(* Logix 5000 project; controller Motion_Axis_AOIs_AMCI_RSLogix_V31 vendor 1 type 14 code 108 rev 31.11; software revision 31.02; part 6 of 7 *)

ADD_ON_INSTRUCTION AMCI_MSO_Enable   (* revision 1.0, vendor AMCI, ExecuteEnableInFalse *)
// AMCI Enable Driver
// Help:
// MSO_ENABLE:   Sends power to the motor.
// This instruction must only be used to change the existing enabled / disabled state of the AMCI motion device.  It MUST NOT be used in an unconditional rung because it will interfere with the other instructions sending data to the motion device
// AXIS INPUT DATA:  Input data from AMCI motion device.   Uses the AMCI_Motion_Axis_Input_Data User Defined Data Type.
// AXIS OUTPUT DATA; Output data from the AOI to the AMCI motion device.   Uses the AMCI_Motion_Axis_Output_Data User Defined Data Type.
// EN (Enable) Set when rung is true, Reset when rung is false
// DN (Done) Set when command is sent to the motion device.  Reset when the rung is false.
VAR_IN_OUT
   Axis_Input_Data : AMCI_Motion_Axis_Input_Data; {required}
   Axis_Output_Data : AMCI_Motion_Axis_Output_Data; {required}
END_VAR
VAR_OUTPUT
   EN : BOOL; {visible}   // set when rung with AOI is true
   DN : BOOL; {access Read Only, visible}   // set when reset error command sent to motion axis
END_VAR
VAR
   command_data_block : INT[10];
        [1]   // Command Bits LSW
        [3]   // Lower Target Position
        [5]   // Lower Programmed Speed
        [0]   // Command Bits MSW
        [2]   // Upper Target Position
        [4]   // Upper Programmed Speed
END_VAR

ROUTINE EnableInFalse   (* ladder *)
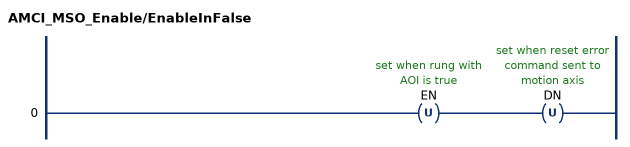
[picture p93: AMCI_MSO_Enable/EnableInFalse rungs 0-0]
   0: OTU(EN)OTU(DN);
END_ROUTINE

ROUTINE Logic   (* ladder *)
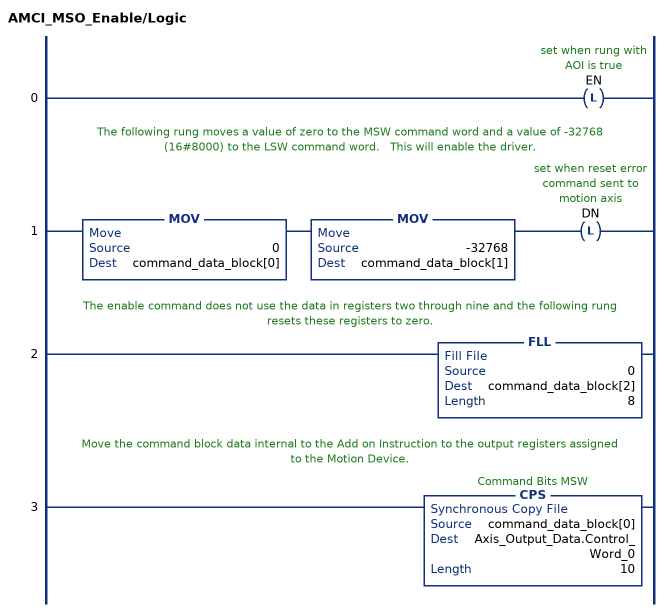
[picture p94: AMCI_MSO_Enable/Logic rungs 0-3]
   0: OTL(EN);
   // The following rung moves a value of zero to the MSW command word and a value of -32768 (16#8000) to the LSW command word.   This will enable the driver.
   1: MOV(0,command_data_block[0])MOV(-32768,command_data_block[1])OTL(DN);
   // The enable command does not use the data in registers two through nine and the following rung resets these registers to zero.
   2: FLL(0,command_data_block[2],8);
   // Move the command block data internal to the Add on Instruction to the output registers assigned to the Motion Device.
   3: CPS(command_data_block[0],Axis_Output_Data.Control_Word_0,10);
END_ROUTINE
END_ADD_ON_INSTRUCTION

VAR_GLOBAL   (* controller tags *)
   AMCI_Motion_Axis_run : DINT;
        .0   // set to run AMCI absolute or relative moves
        .1   // set to stop AMCI Motion
   AMCI_SD17060E2_input_data : AMCI_Motion_Axis_Input_Data;
   AMCI_SD17060E2_output_data : AMCI_Motion_Axis_Output_Data;
   AMCI_SD31045E2_input_data : AMCI_Motion_Axis_Input_Data;
   AMCI_SD31045E2_output_data : AMCI_Motion_Axis_Output_Data;
   AMCI_SD4840E2_input_data : AMCI_Motion_Axis_Input_Data;
   AMCI_SD4840E2_output_data : AMCI_Motion_Axis_Output_Data;
   AMCI_SMD17E2_input_data : AMCI_Motion_Axis_Input_Data;
   AMCI_SMD17E2_output_data : AMCI_Motion_Axis_Output_Data;
   AMCI_SMD23E2_input_data : AMCI_Motion_Axis_Input_Data;
   AMCI_SMD23E2_output_data : AMCI_Motion_Axis_Output_Data;
   AMCI_SMD34E2_input_data : AMCI_Motion_Axis_Input_Data;
   AMCI_SMD34E2_output_data : AMCI_Motion_Axis_Output_Data;
   AMCI_SV160E2_input_data : AMCI_Motion_Axis_Input_Data;
   AMCI_SV160E2_output_data : AMCI_Motion_Axis_Output_Data;
   AMCI_SV4000E2_input_data : AMCI_Motion_Axis_Input_Data;
   AMCI_SV400E2_output_data : AMCI_Motion_Axis_Output_Data;
   comment_coil : DINT;
   Main_Power : BOOL;   // 0=Remove Main Power 1=Apply Main Power
   Run_AMCI_SD17060E2 : DINT;
        .5   // Preset Motor Position. Will also reset Position Invalid Status bit
        .0   // Absolute or Relative Moves
        .1   // CW or CCW Jogs
        .2   // CW or CCW Home
        .3   // Stop Motion
        .4   // Reset Command or Input Errors
        .6   // Linear Axis Follower
        .7   // Circular Axis Follower
        .8   // Reset Driver Fault
   Run_AMCI_SD31045 : DINT;
        .6   // Linear Axis Follower
        .4   // Reset Command or Input Errors
        .1   // CW or CCW Jogs
        .2   // CW or CCW Home
        .3   // Stop Motion
        .5   // Preset Motor Position. Will also reset Position Invalid Status bit
        .8   // Reset Driver Faults
        .0   // Absolute or Relative Moves
        .7   // Circular Axis Follower
   Run_AMCI_SD4840E2 : DINT;
        .4   // Reset Command or Input Errors
        .6   // Linear Axis Follower
        .0   // Absolute or Relative Moves
        .1   // CW or CCW jogs
        .2   // CW or CCW Home
        .3   // Stop Motion
        .7   // Circular Axis Follower
        .5   // Preset Motor Position. Will also reset Position Invalid Status bit
        .8   // Reset Driver Faults
   Run_AMCI_SMD17E2 : DINT;
        .0   // Absolute or Relative Moves
        .6   // Linear Axis Follower
        .1   // CW or CCW Jogs
        .2   // CW or CCW Home
        .3   // Stop Motion
        .4   // Reset Command or Input Errors
        .7   // Circular Axis Follower
        .5   // Preset Motor Position. Will also reset Position Invalid Status bit
        .8   // Enable and Preset Motor Position to Absolute Encoder Position
   Run_AMCI_SMD23_24E2 : DINT;
        .8   // Enable and Preset Motor Position to Absolute Encoder Position
        .0   // Absolute or Relative Moves
        .4   // Reset Command or Input Errors
        .1   // CW or CCW Jogs
        .2   // CW or CCW Home
        .3   // Stop Motion
        .6   // Linear Axis Follower
        .7   // Circular Axis Follower
        .5   // Preset Motor Position. Will also reset Position Invalid Status bit
   Run_AMCI_SMD34E2 : DINT;
        .1   // CW or CCW Jogs
        .4   // Reset Command or Input Errors
        .0   // Absolute or Relative Moves
        .8   // Reset Driver Faults
        .9   // Preset Motor to Encoder
        .2   // CW or CCW Home
        .3   // Stop Motion
        .6   // Linear Axis Follower
        .5   // Preset Motor Position. Will also reset Position Invalid Status bit
        .7   // Circular Axis Follower
   Run_AMCI_SV160E2 : DINT;
        .7   // Circular Axis Follower
        .4   // Reset Command or Input Errors
        .6   // Linear Axis Follower
        .0   // Absolute or Relative Moves
        .1   // CW or CCW Jogs
        .2   // CW or CCW Home
        .3   // Stop Motion
        .5   // Preset Motor Position. Will also reset Position Invalid Status bit
   Run_AMCI_SV400E2 : DINT;
        .0   // Absolute or Relative Moves
        .6   // Linear Axis Follower
        .4   // Reset Command or Input Errors
        .7   // Circular Axis Follower
        .8   // Reset Driver Faults
        .1   // CW or CCW Jogs
        .2   // CW or CCW Home
        .3   // Stop Motion
        .5   // Preset Motor Position. Will also reset Position Invalid Status bit
   Sample_Motion_Axis : AXIS_VIRTUAL;
   Sample_Motion_Group : MOTION_GROUP;
END_VAR

PROGRAM MainProgram   (* main routine MainRoutine *)
VAR
   AMCI_MA_Circular_Follower_SD17060E2 : AMCI_MA_SD_SMD_Circular_Follower;
   AMCI_MA_Circular_Follower_SD31045E2 : AMCI_MA_SD_SMD_Circular_Follower;
   AMCI_MA_Circular_Follower_SD4840E2 : AMCI_MA_SD_SMD_Circular_Follower;
   AMCI_MA_Circular_Follower_SMD17E2 : AMCI_MA_SD_SMD_Circular_Follower;
   AMCI_MA_Circular_Follower_SMD23E2 : AMCI_MA_SD_SMD_Circular_Follower;
   AMCI_MA_Circular_Follower_SMD34E2 : AMCI_MA_SD_SMD_Circular_Follower;
   AMCI_MA_Linear_Follower_SD17060E2 : AMCI_MA_SD_SMD_Linear_Follower;
   AMCI_MA_Linear_Follower_SD31045E2 : AMCI_MA_SD_SMD_Linear_Follower;
   AMCI_MA_Linear_Follower_SD4840E2 : AMCI_MA_SD_SMD_Linear_Follower;
   AMCI_MA_Linear_Follower_SMD17E2 : AMCI_MA_SD_SMD_Linear_Follower;
   AMCI_MA_Linear_Follower_SMD23E2 : AMCI_MA_SD_SMD_Linear_Follower;
   AMCI_MA_Linear_Follower_SMD34E2 : AMCI_MA_SD_SMD_Linear_Follower;
   AMCI_MA_Preset_Encoder : AMCI_MA_Preset_Encoder;
   AMCI_MA_Registration_Move : AMCI_MA_Registration_Move;
   AMCI_MA_Reset_Driver_Fault : AMCI_MA_Reset_Driver_Fault;
   AMCI_MA_Reset_Driver_Faults_SD17060E2 : AMCI_MA_Reset_Driver_Fault;
   AMCI_MA_Reset_Driver_Faults_SD31045E2 : AMCI_MA_Reset_Driver_Fault;
   AMCI_MA_Reset_Driver_Faults_SD4840E2 : AMCI_MA_Reset_Driver_Fault;
   AMCI_MA_Reset_Driver_Faults_SMD34E2 : AMCI_MA_Reset_Driver_Fault;
   AMCI_MAFR_SD17060E2 : AMCI_MAFR;
   AMCI_MAFR_SD31045E2 : AMCI_MAFR;
   AMCI_MAFR_SD4840E2 : AMCI_MAFR;
   AMCI_MAFR_SMD17E2 : AMCI_MAFR;
   AMCI_MAFR_SMD23E2 : AMCI_MAFR;
   AMCI_MAFR_SMD34E2 : AMCI_MAFR;
   AMCI_MAFR_SV160E2 : AMCI_MAFR;
   AMCI_MAFR_SV400E2 : AMCI_MAFR;
   AMCI_MAH_SD17060E2 : AMCI_MAH;
   AMCI_MAH_SD31045E2 : AMCI_MAH;
   AMCI_MAH_SD4840E2 : AMCI_MAH;
   AMCI_MAH_SMD17E2 : AMCI_MAH;
   AMCI_MAH_SMD23E2 : AMCI_MAH;
   AMCI_MAH_SMD34E2 : AMCI_MAH;
   AMCI_MAH_SV160E2 : AMCI_MAH;
   AMCI_MAH_SV400E2 : AMCI_MAH;
   AMCI_MAJ_SD17060E2 : AMCI_MAJ;
   AMCI_MAJ_SD31045E2 : AMCI_MAJ;
   AMCI_MAJ_SD4840E2 : AMCI_MAJ;
   AMCI_MAJ_SMD17E2 : AMCI_MAJ;
   AMCI_MAJ_SMD23E2 : AMCI_MAJ;
   AMCI_MAJ_SMD34E2 : AMCI_MAJ;
   AMCI_MAJ_SV160E2 : AMCI_MAJ;
   AMCI_MAJ_SV400E2 : AMCI_MAJ;
   AMCI_MAM_SD17060E2 : AMCI_MAM;
   AMCI_MAM_SD31045E2 : AMCI_MAM;
   AMCI_MAM_SD48404E2 : AMCI_MAM;
   AMCI_MAM_SMD17E2 : AMCI_MAM;
   AMCI_MAM_SMD23E2 : AMCI_MAM;
   AMCI_MAM_SMD34E2 : AMCI_MAM;
   AMCI_MAM_SV160E2 : AMCI_MAM;
   AMCI_MAM_SV400E2 : AMCI_MAM;
   AMCI_MAS_SD17060E2 : AMCI_MAS;
   AMCI_MAS_SD31045E2 : AMCI_MAS;
   AMCI_MAS_SD4840E2 : AMCI_MAS;
   AMCI_MAS_SMD17E2 : AMCI_MAS;
   AMCI_MAS_SMD23E2 : AMCI_MAS;
   AMCI_MAS_SMD34E2 : AMCI_MAS;
   AMCI_MAS_SV160E2 : AMCI_MAS;
   AMCI_MAS_SV400E2 : AMCI_MAS;
   AMCI_MRP_SD17060E2 : AMCI_MRP;
   AMCI_MRP_SD31045E2 : AMCI_MRP;
   AMCI_MRP_SD4840E2 : AMCI_MRP;
   AMCI_MRP_SMD17E2 : AMCI_MRP;
   AMCI_MRP_SMD23E2 : AMCI_MRP;
   AMCI_MRP_SMD34E2 : AMCI_MRP;
   AMCI_MRP_SV160E2 : AMCI_MRP;
   AMCI_MRP_SV400E2 : AMCI_MRP;
   AMCI_MSF_Disable_SMD23E2 : AMCI_MSF_Disable;
   AMCI_MSO_Enable_SMD23E2 : AMCI_MSO_Enable;
   AMCI_MSO_Preset_to_Absolute_Encoder : AMCI_MSO_and_Preset_to_Absolute_Encoder;
   AMCI_MSO_Preset_to_encoder : AMCI_MSO_and_Preset_to_Absolute_Encoder;
   AMCI_SV160E2_Circular_Follower : AMCI_MA_SV_Circular_Follower;
   AMCI_SV16E2_Linear_Follower : AMCI_MA_SV_Linear_Follower;
   AMCI_SV400E2_Circular_Follower : AMCI_MA_SV_Circular_Follower;
   AMCI_SV400E2_Linear_Follower : AMCI_MA_SV_Linear_Follower;
END_VAR

ROUTINE MainRoutine   (* ladder *)
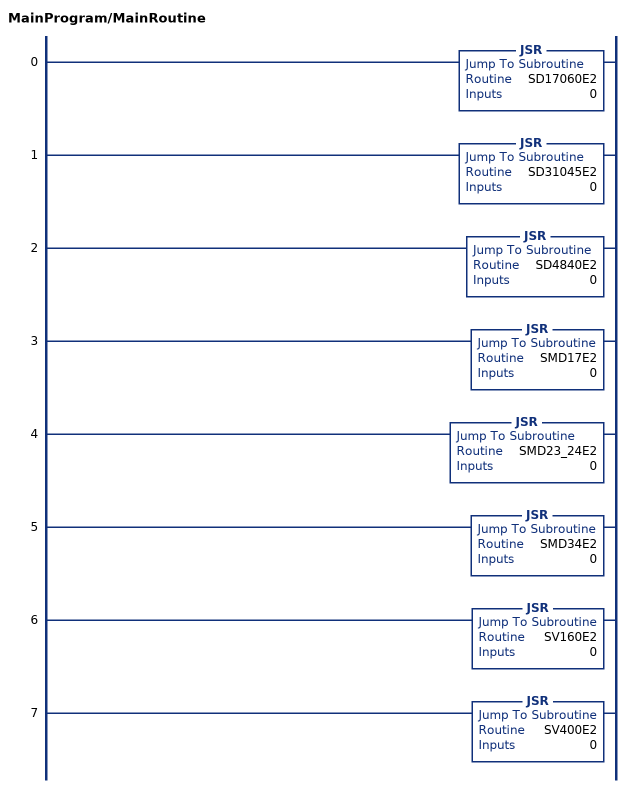
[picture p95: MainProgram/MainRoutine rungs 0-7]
   0: JSR(SD17060E2,0);
   1: JSR(SD31045E2,0);
   2: JSR(SD4840E2,0);
   3: JSR(SMD17E2,0);
   4: JSR(SMD23_24E2,0);
   5: JSR(SMD34E2,0);
   6: JSR(SV160E2,0);
   7: JSR(SV400E2,0);
END_ROUTINE

ROUTINE SD17060E2   (* ladder *)
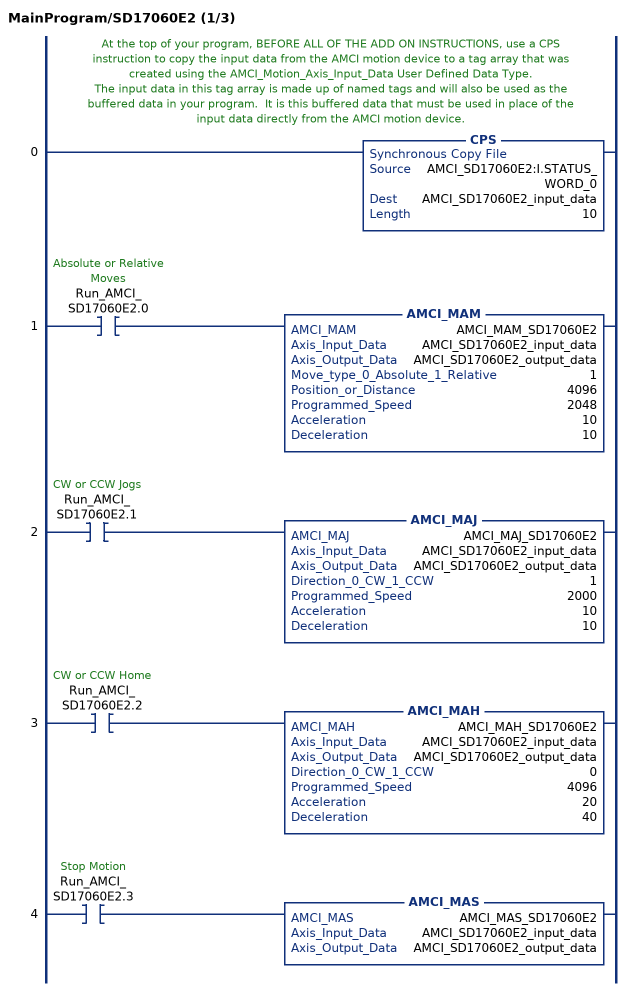
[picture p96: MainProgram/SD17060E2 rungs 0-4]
   // At the top of your program, BEFORE ALL OF THE ADD ON INSTRUCTIONS, use a CPS instruction to copy the input data from the AMCI motion device to a tag array that was created using the AMCI_Motion_Axis_Input_Data User Defined Data Type.
   // The input data in this tag array is made up of named tags and will also be used as the buffered data in your program.  It is this buffered data that must be used in place of the input data directly from the AMCI motion device.
   0: CPS(AMCI_SD17060E2:I.STATUS_WORD_0,AMCI_SD17060E2_input_data,10);
   1: XIC(Run_AMCI_SD17060E2.0)AMCI_MAM(AMCI_MAM_SD17060E2,AMCI_SD17060E2_input_data,AMCI_SD17060E2_output_data,1,4096,2048,10,10);
   2: XIC(Run_AMCI_SD17060E2.1)AMCI_MAJ(AMCI_MAJ_SD17060E2,AMCI_SD17060E2_input_data,AMCI_SD17060E2_output_data,1,2000,10,10);
   3: XIC(Run_AMCI_SD17060E2.2)AMCI_MAH(AMCI_MAH_SD17060E2,AMCI_SD17060E2_input_data,AMCI_SD17060E2_output_data,0,4096,20,40);
   4: XIC(Run_AMCI_SD17060E2.3)AMCI_MAS(AMCI_MAS_SD17060E2,AMCI_SD17060E2_input_data,AMCI_SD17060E2_output_data);
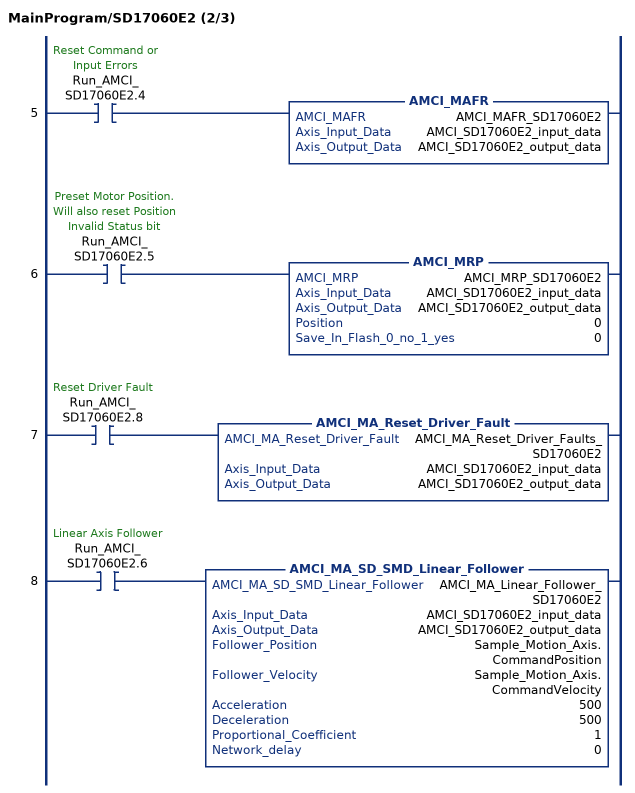
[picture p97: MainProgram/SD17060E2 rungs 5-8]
   5: XIC(Run_AMCI_SD17060E2.4)AMCI_MAFR(AMCI_MAFR_SD17060E2,AMCI_SD17060E2_input_data,AMCI_SD17060E2_output_data);
   6: XIC(Run_AMCI_SD17060E2.5)AMCI_MRP(AMCI_MRP_SD17060E2,AMCI_SD17060E2_input_data,AMCI_SD17060E2_output_data,0,0);
   7: XIC(Run_AMCI_SD17060E2.8)AMCI_MA_Reset_Driver_Fault(AMCI_MA_Reset_Driver_Faults_SD17060E2,AMCI_SD17060E2_input_data,AMCI_SD17060E2_output_data);
   8: XIC(Run_AMCI_SD17060E2.6)AMCI_MA_SD_SMD_Linear_Follower(AMCI_MA_Linear_Follower_SD17060E2,AMCI_SD17060E2_input_data,AMCI_SD17060E2_output_data,Sample_Motion_Axis.CommandPosition,Sample_Motion_Axis.CommandVelocity,500,500,1,0);
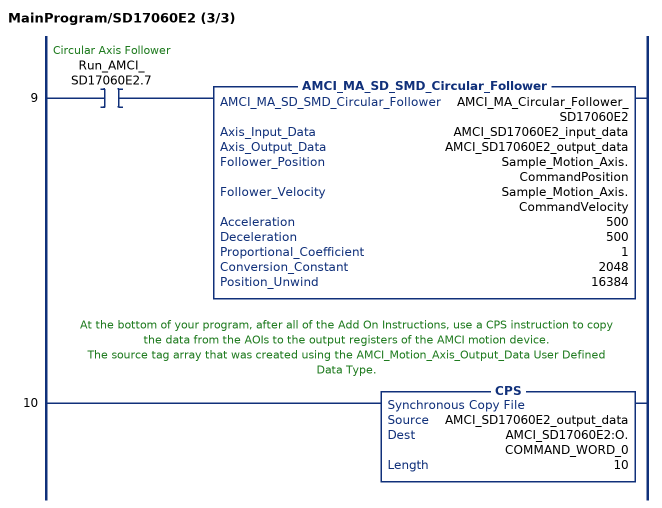
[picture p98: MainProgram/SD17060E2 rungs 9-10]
   9: XIC(Run_AMCI_SD17060E2.7)AMCI_MA_SD_SMD_Circular_Follower(AMCI_MA_Circular_Follower_SD17060E2,AMCI_SD17060E2_input_data,AMCI_SD17060E2_output_data,Sample_Motion_Axis.CommandPosition,Sample_Motion_Axis.CommandVelocity,500,500,1,2048,16384);
   // At the bottom of your program, after all of the Add On Instructions, use a CPS instruction to copy the data from the AOIs to the output registers of the AMCI motion device.
   // The source tag array that was created using the AMCI_Motion_Axis_Output_Data User Defined Data Type.
   10: CPS(AMCI_SD17060E2_output_data,AMCI_SD17060E2:O.COMMAND_WORD_0,10);
END_ROUTINE

ROUTINE SD31045E2   (* ladder *)
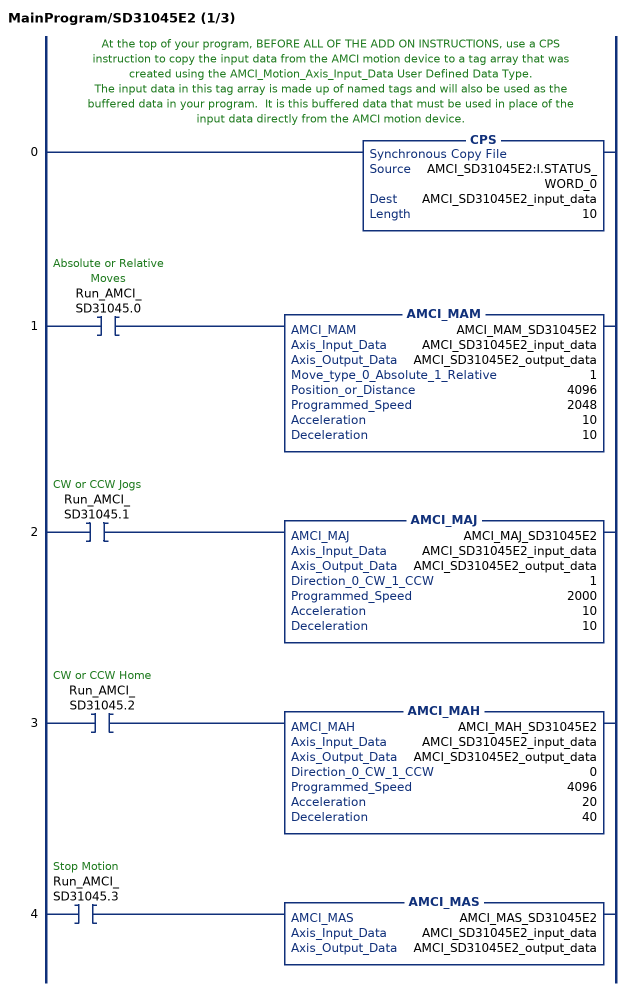
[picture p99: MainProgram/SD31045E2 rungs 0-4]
   // At the top of your program, BEFORE ALL OF THE ADD ON INSTRUCTIONS, use a CPS instruction to copy the input data from the AMCI motion device to a tag array that was created using the AMCI_Motion_Axis_Input_Data User Defined Data Type.
   // The input data in this tag array is made up of named tags and will also be used as the buffered data in your program.  It is this buffered data that must be used in place of the input data directly from the AMCI motion device.
   0: CPS(AMCI_SD31045E2:I.STATUS_WORD_0,AMCI_SD31045E2_input_data,10);
   1: XIC(Run_AMCI_SD31045.0)AMCI_MAM(AMCI_MAM_SD31045E2,AMCI_SD31045E2_input_data,AMCI_SD31045E2_output_data,1,4096,2048,10,10);
   2: XIC(Run_AMCI_SD31045.1)AMCI_MAJ(AMCI_MAJ_SD31045E2,AMCI_SD31045E2_input_data,AMCI_SD31045E2_output_data,1,2000,10,10);
   3: XIC(Run_AMCI_SD31045.2)AMCI_MAH(AMCI_MAH_SD31045E2,AMCI_SD31045E2_input_data,AMCI_SD31045E2_output_data,0,4096,20,40);
   4: XIC(Run_AMCI_SD31045.3)AMCI_MAS(AMCI_MAS_SD31045E2,AMCI_SD31045E2_input_data,AMCI_SD31045E2_output_data);
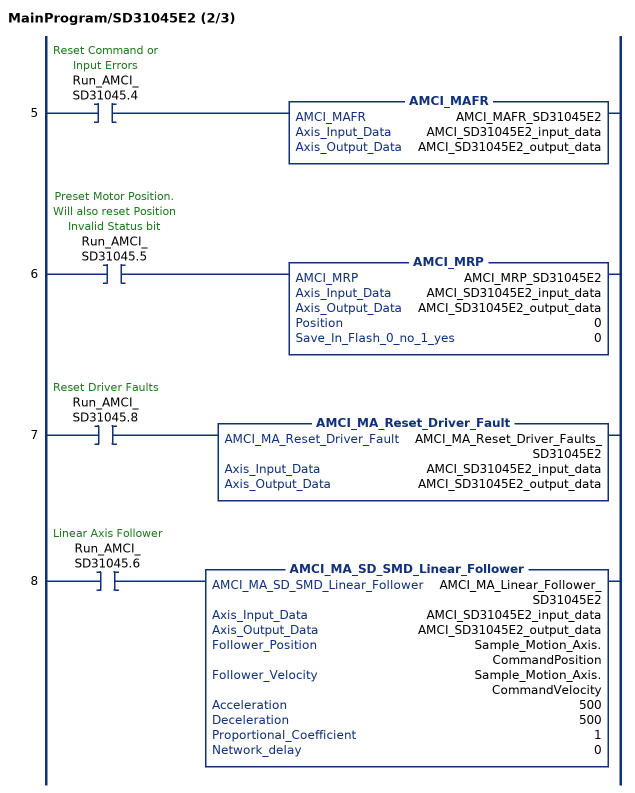
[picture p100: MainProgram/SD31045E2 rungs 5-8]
   5: XIC(Run_AMCI_SD31045.4)AMCI_MAFR(AMCI_MAFR_SD31045E2,AMCI_SD31045E2_input_data,AMCI_SD31045E2_output_data);
   6: XIC(Run_AMCI_SD31045.5)AMCI_MRP(AMCI_MRP_SD31045E2,AMCI_SD31045E2_input_data,AMCI_SD31045E2_output_data,0,0);
   7: XIC(Run_AMCI_SD31045.8)AMCI_MA_Reset_Driver_Fault(AMCI_MA_Reset_Driver_Faults_SD31045E2,AMCI_SD31045E2_input_data,AMCI_SD31045E2_output_data);
   8: XIC(Run_AMCI_SD31045.6)AMCI_MA_SD_SMD_Linear_Follower(AMCI_MA_Linear_Follower_SD31045E2,AMCI_SD31045E2_input_data,AMCI_SD31045E2_output_data,Sample_Motion_Axis.CommandPosition,Sample_Motion_Axis.CommandVelocity,500,500,1,0);
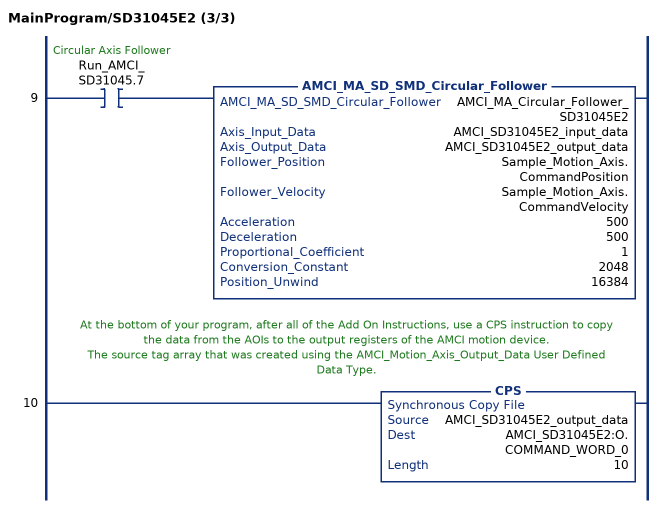
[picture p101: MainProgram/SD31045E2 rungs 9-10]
   9: XIC(Run_AMCI_SD31045.7)AMCI_MA_SD_SMD_Circular_Follower(AMCI_MA_Circular_Follower_SD31045E2,AMCI_SD31045E2_input_data,AMCI_SD31045E2_output_data,Sample_Motion_Axis.CommandPosition,Sample_Motion_Axis.CommandVelocity,500,500,1,2048,16384);
   // At the bottom of your program, after all of the Add On Instructions, use a CPS instruction to copy the data from the AOIs to the output registers of the AMCI motion device.
   // The source tag array that was created using the AMCI_Motion_Axis_Output_Data User Defined Data Type.
   10: CPS(AMCI_SD31045E2_output_data,AMCI_SD31045E2:O.COMMAND_WORD_0,10);
END_ROUTINE

ROUTINE SD4840E2   (* ladder *)
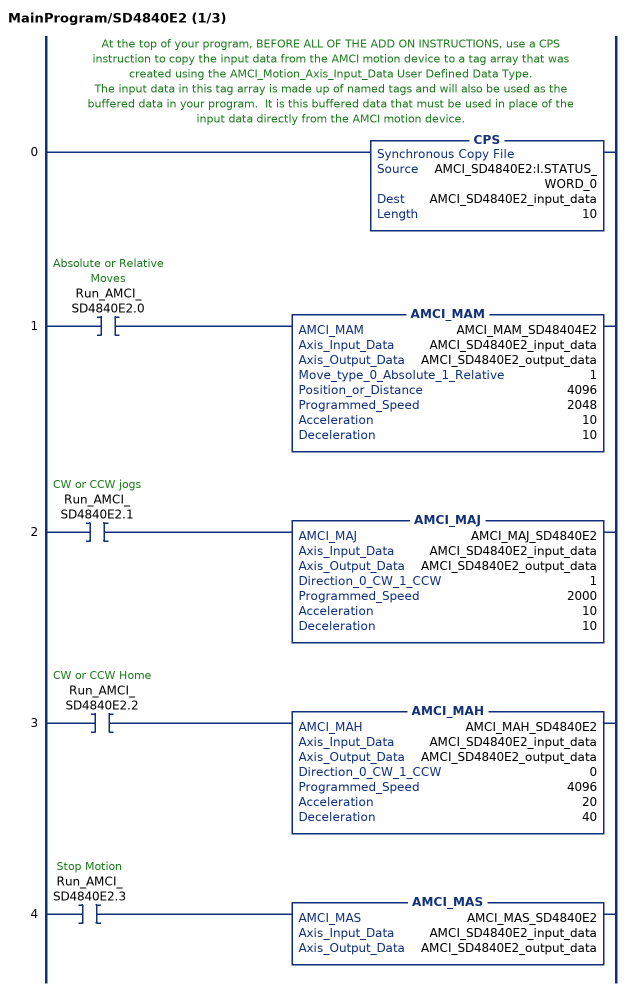
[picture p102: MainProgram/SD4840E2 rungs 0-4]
   // At the top of your program, BEFORE ALL OF THE ADD ON INSTRUCTIONS, use a CPS instruction to copy the input data from the AMCI motion device to a tag array that was created using the AMCI_Motion_Axis_Input_Data User Defined Data Type.
   // The input data in this tag array is made up of named tags and will also be used as the buffered data in your program.  It is this buffered data that must be used in place of the input data directly from the AMCI motion device.
   0: CPS(AMCI_SD4840E2:I.STATUS_WORD_0,AMCI_SD4840E2_input_data,10);
   1: XIC(Run_AMCI_SD4840E2.0)AMCI_MAM(AMCI_MAM_SD48404E2,AMCI_SD4840E2_input_data,AMCI_SD4840E2_output_data,1,4096,2048,10,10);
   2: XIC(Run_AMCI_SD4840E2.1)AMCI_MAJ(AMCI_MAJ_SD4840E2,AMCI_SD4840E2_input_data,AMCI_SD4840E2_output_data,1,2000,10,10);
   3: XIC(Run_AMCI_SD4840E2.2)AMCI_MAH(AMCI_MAH_SD4840E2,AMCI_SD4840E2_input_data,AMCI_SD4840E2_output_data,0,4096,20,40);
   4: XIC(Run_AMCI_SD4840E2.3)AMCI_MAS(AMCI_MAS_SD4840E2,AMCI_SD4840E2_input_data,AMCI_SD4840E2_output_data);
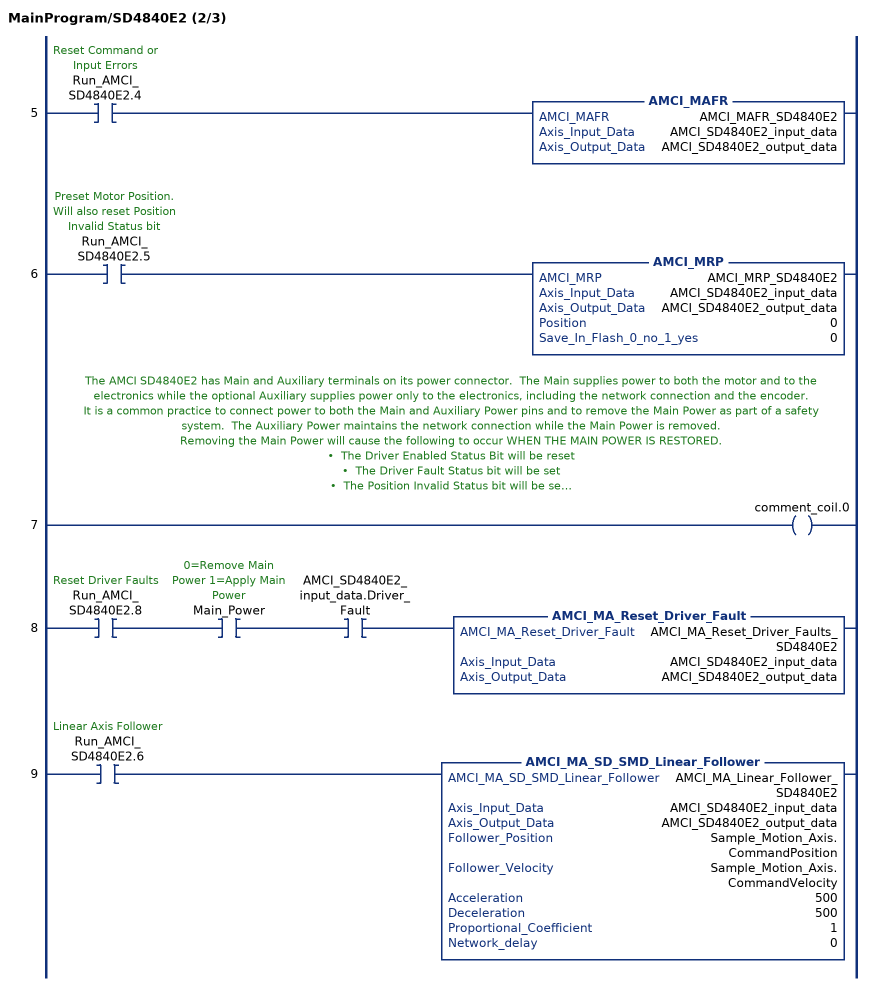
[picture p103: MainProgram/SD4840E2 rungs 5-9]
   5: XIC(Run_AMCI_SD4840E2.4)AMCI_MAFR(AMCI_MAFR_SD4840E2,AMCI_SD4840E2_input_data,AMCI_SD4840E2_output_data);
   6: XIC(Run_AMCI_SD4840E2.5)AMCI_MRP(AMCI_MRP_SD4840E2,AMCI_SD4840E2_input_data,AMCI_SD4840E2_output_data,0,0);
   // The AMCI SD4840E2 has Main and Auxiliary terminals on its power connector.  The Main supplies power to both the motor and to the electronics while the optional Auxiliary supplies power only to the electronics, including the network connection and the encoder.
   // It is a common practice to connect power to both the Main and Auxiliary Power pins and to remove the Main Power as part of a safety system.  The Auxiliary Power maintains the network connection while the Main Power is removed.
   // Removing the Main Power will cause the following to occur WHEN THE MAIN POWER IS RESTORED.
   // •	The Driver Enabled Status Bit will be reset
   // •	The Driver Fault Status bit will be set
   // •	The Position Invalid Status bit will be set
   // The following rung shows the action that you should take after the Main Power has been restored.
   7: OTE(comment_coil.0);
   8: XIC(Run_AMCI_SD4840E2.8)XIC(Main_Power)XIC(AMCI_SD4840E2_input_data.Driver_Fault)AMCI_MA_Reset_Driver_Fault(AMCI_MA_Reset_Driver_Faults_SD4840E2,AMCI_SD4840E2_input_data,AMCI_SD4840E2_output_data);
   9: XIC(Run_AMCI_SD4840E2.6)AMCI_MA_SD_SMD_Linear_Follower(AMCI_MA_Linear_Follower_SD4840E2,AMCI_SD4840E2_input_data,AMCI_SD4840E2_output_data,Sample_Motion_Axis.CommandPosition,Sample_Motion_Axis.CommandVelocity,500,500,1,0);
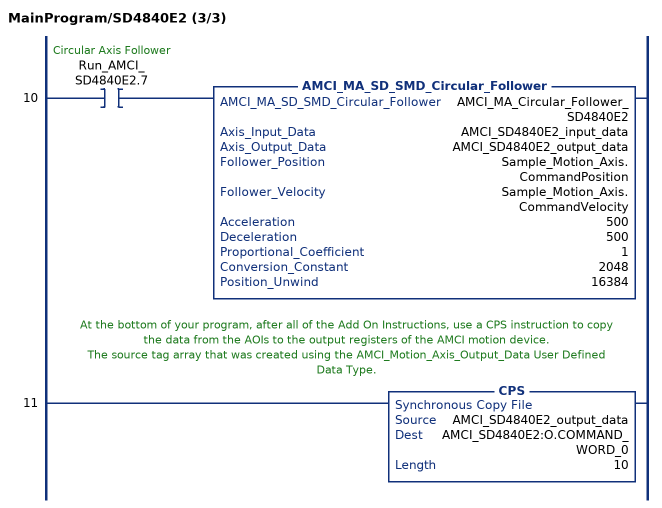
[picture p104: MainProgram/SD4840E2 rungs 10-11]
   10: XIC(Run_AMCI_SD4840E2.7)AMCI_MA_SD_SMD_Circular_Follower(AMCI_MA_Circular_Follower_SD4840E2,AMCI_SD4840E2_input_data,AMCI_SD4840E2_output_data,Sample_Motion_Axis.CommandPosition,Sample_Motion_Axis.CommandVelocity,500,500,1,2048,16384);
   // At the bottom of your program, after all of the Add On Instructions, use a CPS instruction to copy the data from the AOIs to the output registers of the AMCI motion device.
   // The source tag array that was created using the AMCI_Motion_Axis_Output_Data User Defined Data Type.
   11: CPS(AMCI_SD4840E2_output_data,AMCI_SD4840E2:O.COMMAND_WORD_0,10);
END_ROUTINE

ROUTINE SMD17E2   (* ladder *)
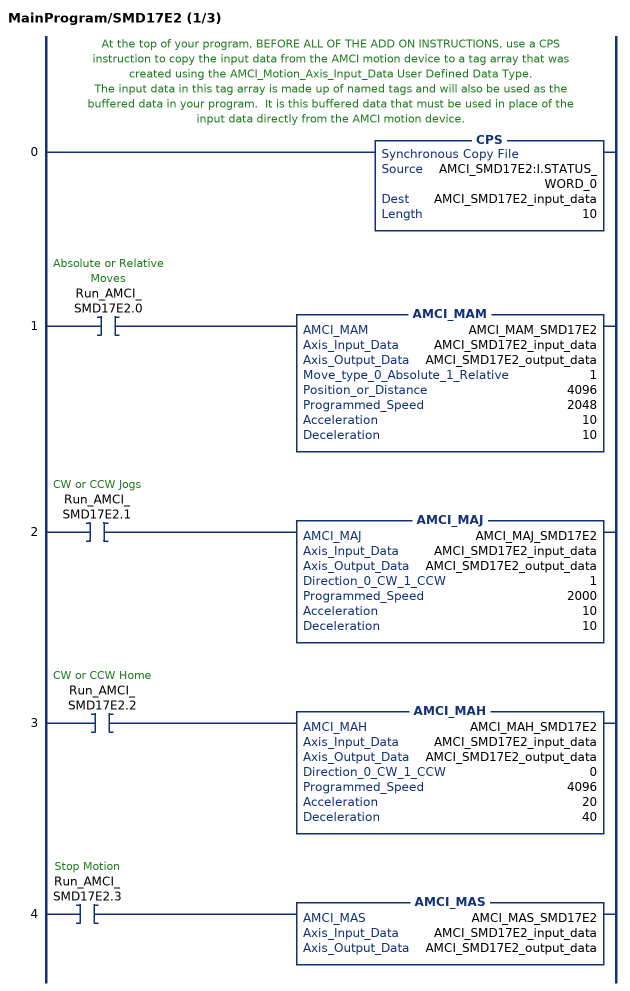
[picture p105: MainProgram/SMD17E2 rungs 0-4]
   // At the top of your program, BEFORE ALL OF THE ADD ON INSTRUCTIONS, use a CPS instruction to copy the input data from the AMCI motion device to a tag array that was created using the AMCI_Motion_Axis_Input_Data User Defined Data Type.
   // The input data in this tag array is made up of named tags and will also be used as the buffered data in your program.  It is this buffered data that must be used in place of the input data directly from the AMCI motion device.
   0: CPS(AMCI_SMD17E2:I.STATUS_WORD_0,AMCI_SMD17E2_input_data,10);
   1: XIC(Run_AMCI_SMD17E2.0)AMCI_MAM(AMCI_MAM_SMD17E2,AMCI_SMD17E2_input_data,AMCI_SMD17E2_output_data,1,4096,2048,10,10);
   2: XIC(Run_AMCI_SMD17E2.1)AMCI_MAJ(AMCI_MAJ_SMD17E2,AMCI_SMD17E2_input_data,AMCI_SMD17E2_output_data,1,2000,10,10);
   3: XIC(Run_AMCI_SMD17E2.2)AMCI_MAH(AMCI_MAH_SMD17E2,AMCI_SMD17E2_input_data,AMCI_SMD17E2_output_data,0,4096,20,40);
   4: XIC(Run_AMCI_SMD17E2.3)AMCI_MAS(AMCI_MAS_SMD17E2,AMCI_SMD17E2_input_data,AMCI_SMD17E2_output_data);
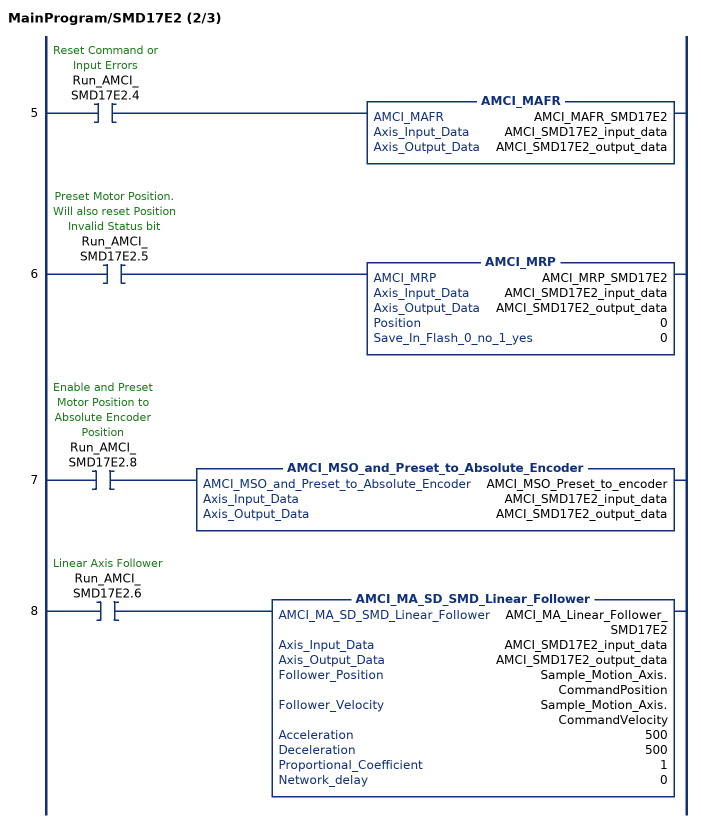
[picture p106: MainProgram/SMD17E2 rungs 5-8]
   5: XIC(Run_AMCI_SMD17E2.4)AMCI_MAFR(AMCI_MAFR_SMD17E2,AMCI_SMD17E2_input_data,AMCI_SMD17E2_output_data);
   6: XIC(Run_AMCI_SMD17E2.5)AMCI_MRP(AMCI_MRP_SMD17E2,AMCI_SMD17E2_input_data,AMCI_SMD17E2_output_data,0,0);
   7: XIC(Run_AMCI_SMD17E2.8)AMCI_MSO_and_Preset_to_Absolute_Encoder(AMCI_MSO_Preset_to_encoder,AMCI_SMD17E2_input_data,AMCI_SMD17E2_output_data);
   8: XIC(Run_AMCI_SMD17E2.6)AMCI_MA_SD_SMD_Linear_Follower(AMCI_MA_Linear_Follower_SMD17E2,AMCI_SMD17E2_input_data,AMCI_SMD17E2_output_data,Sample_Motion_Axis.CommandPosition,Sample_Motion_Axis.CommandVelocity,500,500,1,0);
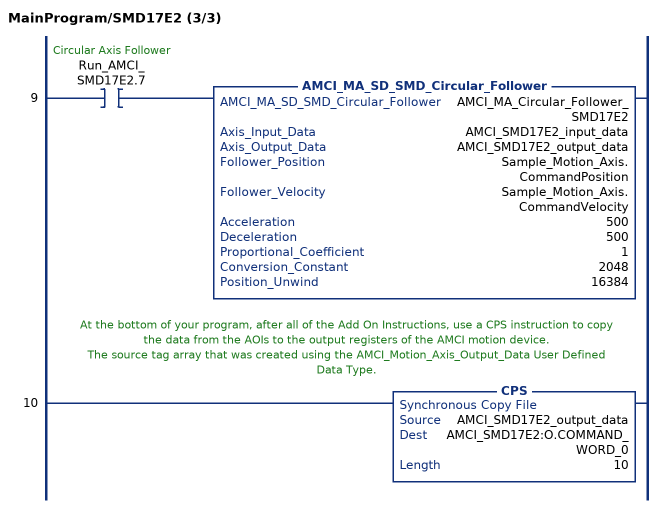
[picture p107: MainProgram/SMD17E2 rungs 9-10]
   9: XIC(Run_AMCI_SMD17E2.7)AMCI_MA_SD_SMD_Circular_Follower(AMCI_MA_Circular_Follower_SMD17E2,AMCI_SMD17E2_input_data,AMCI_SMD17E2_output_data,Sample_Motion_Axis.CommandPosition,Sample_Motion_Axis.CommandVelocity,500,500,1,2048,16384);
   // At the bottom of your program, after all of the Add On Instructions, use a CPS instruction to copy the data from the AOIs to the output registers of the AMCI motion device.
   // The source tag array that was created using the AMCI_Motion_Axis_Output_Data User Defined Data Type.
   10: CPS(AMCI_SMD17E2_output_data,AMCI_SMD17E2:O.COMMAND_WORD_0,10);
END_ROUTINE

ROUTINE SMD23_24E2   (* ladder *)
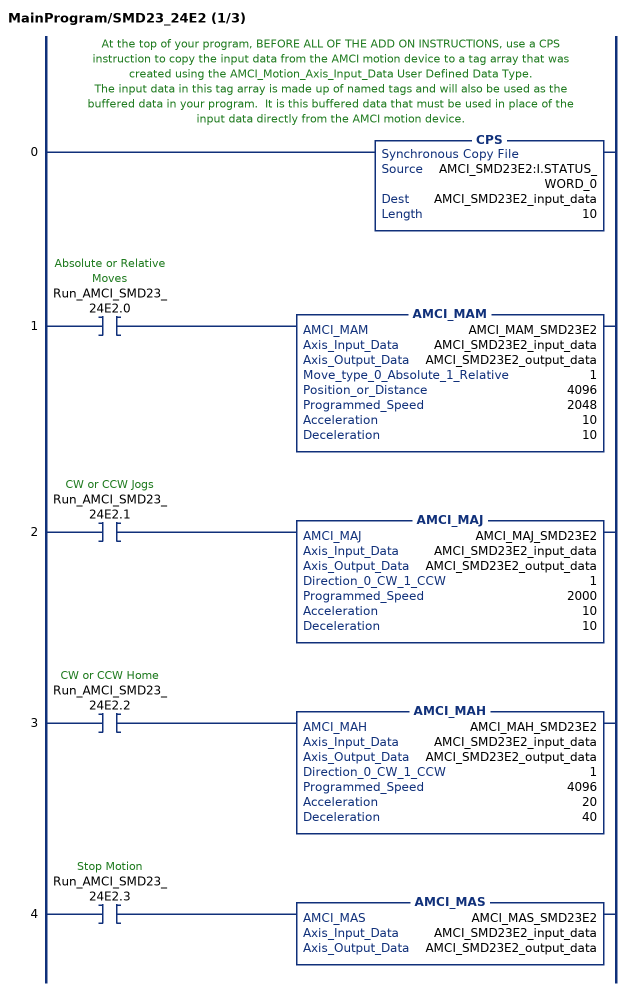
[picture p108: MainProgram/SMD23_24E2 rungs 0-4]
   // At the top of your program, BEFORE ALL OF THE ADD ON INSTRUCTIONS, use a CPS instruction to copy the input data from the AMCI motion device to a tag array that was created using the AMCI_Motion_Axis_Input_Data User Defined Data Type.
   // The input data in this tag array is made up of named tags and will also be used as the buffered data in your program.  It is this buffered data that must be used in place of the input data directly from the AMCI motion device.
   0: CPS(AMCI_SMD23E2:I.STATUS_WORD_0,AMCI_SMD23E2_input_data,10);
   1: XIC(Run_AMCI_SMD23_24E2.0)AMCI_MAM(AMCI_MAM_SMD23E2,AMCI_SMD23E2_input_data,AMCI_SMD23E2_output_data,1,4096,2048,10,10);
   2: XIC(Run_AMCI_SMD23_24E2.1)AMCI_MAJ(AMCI_MAJ_SMD23E2,AMCI_SMD23E2_input_data,AMCI_SMD23E2_output_data,1,2000,10,10);
   3: XIC(Run_AMCI_SMD23_24E2.2)AMCI_MAH(AMCI_MAH_SMD23E2,AMCI_SMD23E2_input_data,AMCI_SMD23E2_output_data,1,4096,20,40);
   4: XIC(Run_AMCI_SMD23_24E2.3)AMCI_MAS(AMCI_MAS_SMD23E2,AMCI_SMD23E2_input_data,AMCI_SMD23E2_output_data);
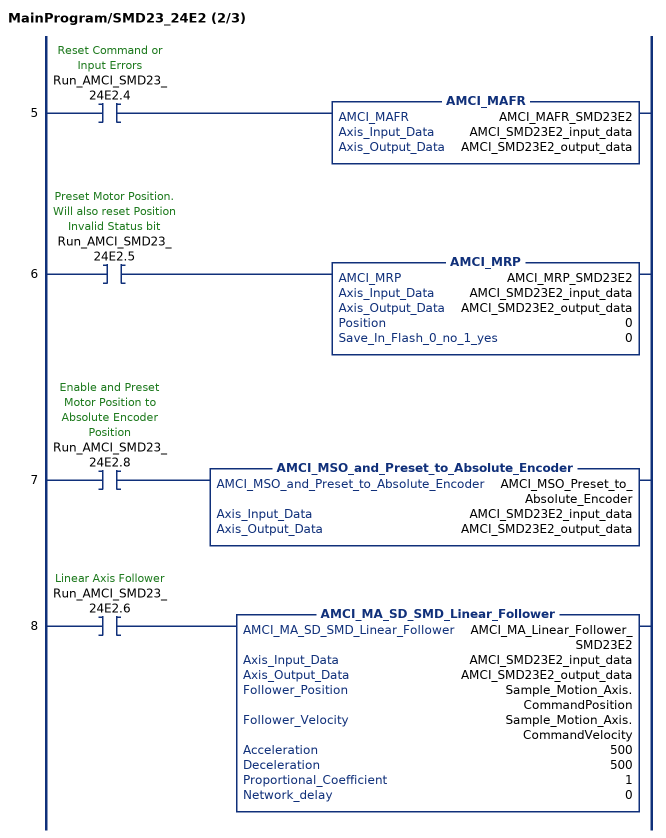
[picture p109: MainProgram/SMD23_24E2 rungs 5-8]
   5: XIC(Run_AMCI_SMD23_24E2.4)AMCI_MAFR(AMCI_MAFR_SMD23E2,AMCI_SMD23E2_input_data,AMCI_SMD23E2_output_data);
   6: XIC(Run_AMCI_SMD23_24E2.5)AMCI_MRP(AMCI_MRP_SMD23E2,AMCI_SMD23E2_input_data,AMCI_SMD23E2_output_data,0,0);
   7: XIC(Run_AMCI_SMD23_24E2.8)AMCI_MSO_and_Preset_to_Absolute_Encoder(AMCI_MSO_Preset_to_Absolute_Encoder,AMCI_SMD23E2_input_data,AMCI_SMD23E2_output_data);
   8: XIC(Run_AMCI_SMD23_24E2.6)AMCI_MA_SD_SMD_Linear_Follower(AMCI_MA_Linear_Follower_SMD23E2,AMCI_SMD23E2_input_data,AMCI_SMD23E2_output_data,Sample_Motion_Axis.CommandPosition,Sample_Motion_Axis.CommandVelocity,500,500,1,0);
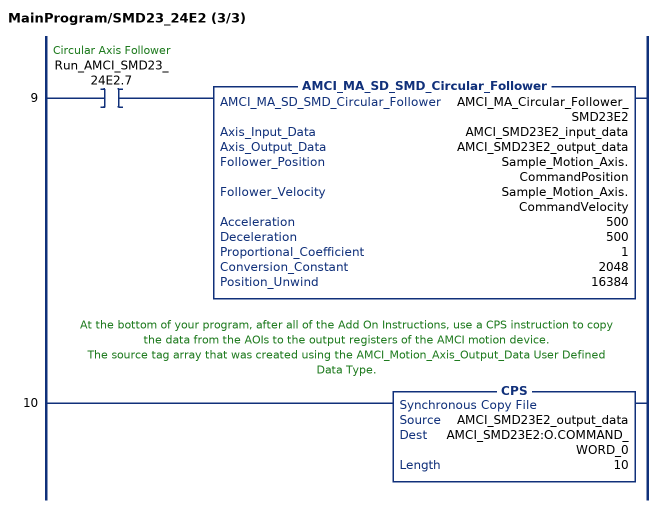
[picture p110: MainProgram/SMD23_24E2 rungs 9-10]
   9: XIC(Run_AMCI_SMD23_24E2.7)AMCI_MA_SD_SMD_Circular_Follower(AMCI_MA_Circular_Follower_SMD23E2,AMCI_SMD23E2_input_data,AMCI_SMD23E2_output_data,Sample_Motion_Axis.CommandPosition,Sample_Motion_Axis.CommandVelocity,500,500,1,2048,16384);
   // At the bottom of your program, after all of the Add On Instructions, use a CPS instruction to copy the data from the AOIs to the output registers of the AMCI motion device.
   // The source tag array that was created using the AMCI_Motion_Axis_Output_Data User Defined Data Type.
   10: CPS(AMCI_SMD23E2_output_data,AMCI_SMD23E2:O.COMMAND_WORD_0,10);
END_ROUTINE
